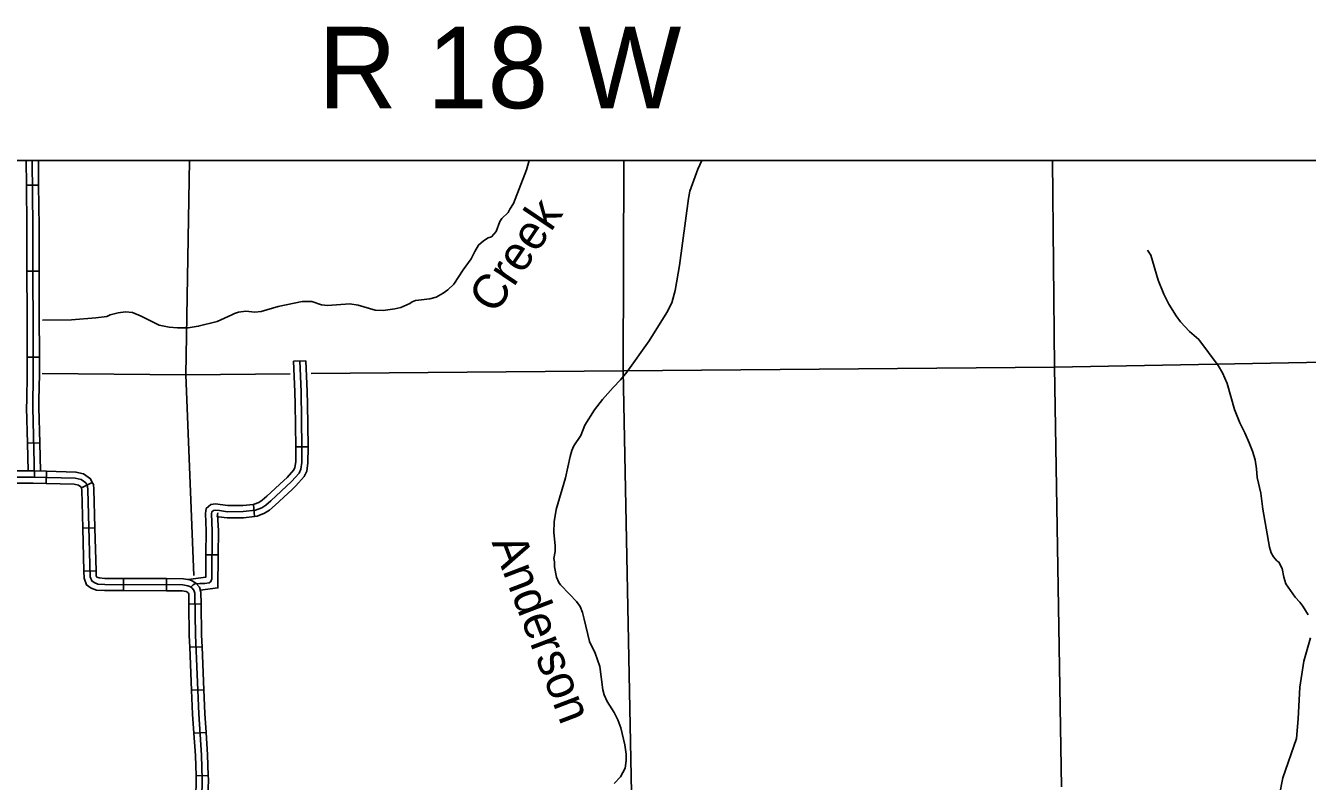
# Model space of a CAD drawing. Extents: x 1373862 to 1376999, y 1168398 to 1170455.
# Drawn here: x 1375095.6 to 1375410.3, y 1169426.9 to 1169612.5 of the extents above; entities that cross this region are included whole.
import ezdxf

# ---------------------------------------------------------------- set-up
doc = ezdxf.new("R2010")
doc.units = 0
for name, color, linetype in [('Level 32', 7, 'Continuous'), ('Level 35', 7, 'Continuous'), ('Level 45', 7, 'Continuous'), ('Level 5', 7, 'Continuous'), ('Level 8', 7, 'Continuous'), ('R_Draft', 7, 'Continuous')]:
    doc.layers.add(name, color=color, linetype=linetype)

msp = doc.modelspace()

# ---------------------------------------------------------------- linework, layer by layer
at = {"layer": 'Level 32'}
for p, q in [((1375100.63, 1169500.05), (1375100.71, 1169503.05)), ((1375109.25, 1169498.98), (1375111.93, 1169500.32)), ((1375109.58, 1169489.09), (1375112.58, 1169489.17)), ((1375109.86, 1169478.54), (1375112.86, 1169478.62)), ((1375119.59, 1169473.73), (1375119.6, 1169476.73)), ((1375130.15, 1169473.69), (1375130.16, 1169476.69)), ((1375135.64, 1169470.42), (1375138.64, 1169470.47)), ((1375135.87, 1169459.82), (1375138.87, 1169459.95)), ((1375136.32, 1169449.27), (1375139.32, 1169449.4)), ((1375136.88, 1169438.7), (1375139.87, 1169438.89)), ((1375137.39, 1169428.2), (1375140.39, 1169428.29))]:
    msp.add_line(p, q, dxfattribs=at)
for points in [[(1375090.11, 1169503.13), (1375097.42, 1169503.14), (1375100.71, 1169503.05)], [(1375100.71, 1169503.05), (1375107.89, 1169502.86), (1375109.78, 1169502.42), (1375111.49, 1169501.21), (1375111.93, 1169500.32)], [(1375063.64, 1169501.6), (1375097.4, 1169501.64), (1375107.7, 1169501.36), (1375109.15, 1169501.02), (1375110.31, 1169500.2), (1375110.72, 1169499.38), (1375110.83, 1169498.52), (1375111.39, 1169477.11), (1375111.77, 1169476.1), (1375112.37, 1169475.69), (1375113.3, 1169475.36), (1375114.98, 1169475.24), (1375134.15, 1169475.17), (1375135.42, 1169474.95), (1375135.9, 1169474.72), (1375136.39, 1169474.39), (1375136.87, 1169473.83), (1375137.1, 1169473.12), (1375137.25, 1169462.78), (1375138.07, 1169443.48), (1375138.74, 1169433.3), (1375138.92, 1169427.3), (1375138.81, 1169422.79)], [(1375090.12, 1169500.13), (1375097.38, 1169500.14), (1375100.63, 1169500.05)], [(1375100.63, 1169500.05), (1375107.51, 1169499.87), (1375108.53, 1169499.63), (1375109.14, 1169499.2), (1375109.25, 1169498.98)], [(1375109.25, 1169498.98), (1375109.27, 1169498.94), (1375109.34, 1169498.4), (1375109.58, 1169489.09)], [(1375111.93, 1169500.32), (1375112.18, 1169499.82), (1375112.33, 1169498.64), (1375112.58, 1169489.17)], [(1375109.58, 1169489.09), (1375109.86, 1169478.54)], [(1375112.58, 1169489.17), (1375112.86, 1169478.62)], [(1375109.86, 1169478.54), (1375109.9, 1169476.83), (1375110.53, 1169475.14), (1375111.68, 1169474.35), (1375112.99, 1169473.87), (1375114.93, 1169473.75), (1375119.59, 1169473.73)], [(1375112.86, 1169478.62), (1375112.89, 1169477.4), (1375113.01, 1169477.07), (1375113.06, 1169477.04), (1375113.61, 1169476.84), (1375115.03, 1169476.74), (1375119.6, 1169476.73)], [(1375119.6, 1169476.73), (1375130.16, 1169476.69)], [(1375119.59, 1169473.73), (1375130.15, 1169473.69)], [(1375130.15, 1169473.69), (1375134.01, 1169473.67), (1375134.97, 1169473.5), (1375135.16, 1169473.41), (1375135.38, 1169473.26), (1375135.54, 1169473.08), (1375135.6, 1169472.87), (1375135.64, 1169470.42)], [(1375130.16, 1169476.69), (1375134.28, 1169476.67), (1375135.87, 1169476.39), (1375136.65, 1169476.03), (1375137.4, 1169475.51), (1375138.21, 1169474.57), (1375138.59, 1169473.36), (1375138.64, 1169470.47)], [(1375138.64, 1169470.47), (1375138.75, 1169462.82), (1375138.87, 1169459.95)], [(1375135.64, 1169470.42), (1375135.75, 1169462.73), (1375135.87, 1169459.82)], [(1375135.87, 1169459.82), (1375136.32, 1169449.27)], [(1375138.87, 1169459.95), (1375139.32, 1169449.4)], [(1375136.32, 1169449.27), (1375136.57, 1169443.4), (1375136.88, 1169438.7)], [(1375139.32, 1169449.4), (1375139.57, 1169443.57), (1375139.87, 1169438.89)], [(1375136.88, 1169438.7), (1375137.24, 1169433.23), (1375137.39, 1169428.2)], [(1375139.87, 1169438.89), (1375140.23, 1169433.38), (1375140.39, 1169428.29)], [(1375137.39, 1169428.2), (1375137.42, 1169427.3), (1375137.31, 1169422.87), (1375136.93, 1169417.82)], [(1375140.39, 1169428.29), (1375140.42, 1169427.31), (1375140.31, 1169422.72), (1375139.92, 1169417.59)]]:
    msp.add_lwpolyline(points, dxfattribs=at)
at = {"layer": 'Level 35'}
for points in [[(1375099.73, 1169540.16), (1375106.79, 1169540.27), (1375112.76, 1169540.73), (1375115.51, 1169541.11), (1375116.32, 1169541.47), (1375118.25, 1169541.96), (1375120.1, 1169542.19), (1375121.79, 1169542.04), (1375123.93, 1169541.15), (1375128.35, 1169538.98), (1375130.84, 1169538.43), (1375132.87, 1169538.3), (1375135.45, 1169538.33), (1375137.96, 1169538.7), (1375142.59, 1169539.87), (1375146.17, 1169541.45), (1375146.84, 1169541.85), (1375147.85, 1169542.15), (1375149.6, 1169542.42), (1375151.85, 1169542.14), (1375153.36, 1169542.3), (1375157.55, 1169543.5), (1375163.48, 1169544.78), (1375165.86, 1169544.74), (1375168.18, 1169543.98), (1375169.71, 1169543.74), (1375175.16, 1169544.19), (1375177.19, 1169543.84), (1375181.42, 1169542.63), (1375183.36, 1169542.54), (1375186.21, 1169542.98), (1375187.66, 1169543.32), (1375189.88, 1169544.28), (1375190.51, 1169544.7), (1375191.26, 1169545), (1375194.83, 1169545.38), (1375196.36, 1169545.82), (1375198.09, 1169546.81), (1375199.27, 1169547.64), (1375200.67, 1169549), (1375203.02, 1169552.58), (1375204.99, 1169555.24), (1375205.83, 1169557.05), (1375206.8, 1169558.64), (1375207.98, 1169559.69), (1375209.16, 1169560.37), (1375209.93, 1169560.67), (1375211.14, 1169561.92), (1375211.97, 1169564.43), (1375212.49, 1169565.15), (1375214.04, 1169566.64), (1375214.43, 1169567.45), (1375215.36, 1169568.82), (1375218.56, 1169577.11), (1375219.24, 1169579.43)], [(1375261.57, 1169579.43), (1375260.64, 1169577.31), (1375258.7, 1169571.86), (1375258.31, 1169570.07), (1375256.14, 1169553.58), (1375255.04, 1169547.47), (1375254.22, 1169544.44), (1375253, 1169542.1), (1375248.66, 1169535.12), (1375243.22, 1169527.37), (1375241.63, 1169525.51), (1375239.86, 1169523.67), (1375237.18, 1169520.67), (1375235.24, 1169518.15), (1375232.84, 1169514.38), (1375231.93, 1169511.86), (1375230.15, 1169509.31), (1375229.68, 1169508.19), (1375229.24, 1169506.7), (1375228.14, 1169501.47), (1375225.8, 1169493.67), (1375225.34, 1169490.6), (1375225.29, 1169488.01), (1375225.59, 1169484.81), (1375225.63, 1169483.33), (1375225.26, 1169481.63), (1375225.4, 1169480.81), (1375225.45, 1169479.59), (1375225.94, 1169477.04), (1375226.49, 1169475.71), (1375226.88, 1169475.16), (1375229.07, 1169472.83), (1375230.85, 1169471.09), (1375231.7, 1169469.87), (1375232.32, 1169468.36), (1375232.74, 1169466.75)], [(1375371.05, 1169557.4), (1375371.87, 1169556.12), (1375373.69, 1169549.99), (1375375.08, 1169546.57), (1375376.28, 1169544.12), (1375378.06, 1169541.26), (1375379.14, 1169539.74), (1375381.38, 1169537.43), (1375383.65, 1169535.41), (1375388.42, 1169529.04), (1375389.46, 1169527.24), (1375390.59, 1169524.6), (1375392.4, 1169518.27), (1375393.72, 1169514.96), (1375394.95, 1169512.48), (1375395.99, 1169510.08), (1375396.83, 1169507.96), (1375397.52, 1169505.83), (1375397.82, 1169503.67), (1375397.98, 1169501.51), (1375398.88, 1169497.7), (1375399.4, 1169493.72), (1375401.02, 1169484.4), (1375401.44, 1169483.02), (1375401.96, 1169482.07), (1375402.81, 1169481.09), (1375403.34, 1169480.73), (1375404.1, 1169479.18), (1375404.54, 1169477.01), (1375405, 1169475.43), (1375407.34, 1169472.13), (1375408.48, 1169470.89), (1375409.2, 1169469.93), (1375410.54, 1169467.82)], [(1375232.74, 1169466.75), (1375234.01, 1169461.26), (1375235.4, 1169458.39), (1375236.57, 1169455.09), (1375237.32, 1169449.4), (1375237.61, 1169448.12), (1375238.33, 1169446.53), (1375240.1, 1169443.81), (1375241.01, 1169442.01), (1375241.7, 1169440.06), (1375242.69, 1169435.84), (1375242.99, 1169433.54), (1375243.05, 1169432.04), (1375242.76, 1169430.14), (1375241.66, 1169428.01), (1375240.1, 1169426.38)], [(1375411.1, 1169462.16), (1375409.42, 1169456.37), (1375408.48, 1169450.05), (1375408.06, 1169442.25), (1375407.63, 1169437.39), (1375404.32, 1169427.73), (1375403.4, 1169423.15)]]:
    msp.add_lwpolyline(points, dxfattribs=at)
at = {"layer": 'Level 45'}
for p, q in [((1375095.75, 1169573.31), (1375098.75, 1169573.34)), ((1375095.88, 1169552.2), (1375098.88, 1169552.21)), ((1375095.92, 1169531.08), (1375098.92, 1169531.09)), ((1375161.36, 1169530.09), (1375164.35, 1169530.22)), ((1375096.03, 1169509.93), (1375099.03, 1169510.01)), ((1375161.91, 1169509.02), (1375164.91, 1169509.07)), ((1375151.47, 1169494.93), (1375151.79, 1169491.95)), ((1375139.84, 1169482.53), (1375142.84, 1169482.51))]:
    msp.add_line(p, q, dxfattribs=at)
for points in [[(1375095.69, 1169579.43), (1375095.75, 1169573.31)], [(1375097.19, 1169579.43), (1375097.36, 1169563.21), (1375097.43, 1169526.92), (1375097.29, 1169518.67), (1375097.75, 1169501.63)], [(1375098.69, 1169579.43), (1375098.75, 1169573.34)], [(1375095.75, 1169573.31), (1375095.86, 1169563.2), (1375095.86, 1169562.76)], [(1375098.75, 1169573.34), (1375098.86, 1169563.22), (1375098.86, 1169562.77)], [(1375095.86, 1169562.76), (1375095.88, 1169552.2)], [(1375098.86, 1169562.77), (1375098.88, 1169552.21)], [(1375095.88, 1169552.2), (1375095.9, 1169541.64)], [(1375098.88, 1169552.21), (1375098.9, 1169541.65)], [(1375095.9, 1169541.64), (1375095.92, 1169531.08)], [(1375098.9, 1169541.65), (1375098.92, 1169531.09)], [(1375095.92, 1169531.08), (1375095.93, 1169526.93), (1375095.82, 1169520.55)], [(1375098.92, 1169531.09), (1375098.93, 1169526.91), (1375098.82, 1169520.5)], [(1375162.85, 1169530.16), (1375163.18, 1169522.57), (1375163.41, 1169508.99), (1375163.38, 1169505.23), (1375163.12, 1169503.54), (1375162.69, 1169502.59), (1375160.84, 1169500.51), (1375155.8, 1169495.83), (1375154.55, 1169494.74), (1375153.52, 1169494.08), (1375152.01, 1169493.48), (1375148.97, 1169493.15), (1375145.15, 1169493.12), (1375143.14, 1169493.38), (1375142.15, 1169493.52), (1375141.69, 1169493.45), (1375141.29, 1169493.12), (1375141.19, 1169492.56), (1375141.39, 1169488.41), (1375141.29, 1169476.6), (1375141.06, 1169475.95), (1375140.6, 1169475.62), (1375139.58, 1169475.48), (1375138.36, 1169475.48), (1375137.11, 1169475.38), (1375136.68, 1169475.12), (1375136.14, 1169474.56)], [(1375161.36, 1169530.09), (1375161.68, 1169522.53), (1375161.73, 1169519.58)], [(1375164.35, 1169530.22), (1375164.68, 1169522.62), (1375164.73, 1169519.63)], [(1375095.82, 1169520.55), (1375095.79, 1169518.66), (1375096.03, 1169509.93)], [(1375098.82, 1169520.5), (1375098.79, 1169518.68), (1375099.03, 1169510.01)], [(1375161.73, 1169519.58), (1375161.91, 1169509.02)], [(1375164.73, 1169519.63), (1375164.91, 1169509.07)], [(1375096.03, 1169509.93), (1375096.21, 1169503.14)], [(1375099.03, 1169510.01), (1375099.21, 1169503.09)], [(1375161.91, 1169509.02), (1375161.91, 1169508.98), (1375161.88, 1169505.35), (1375161.67, 1169503.97), (1375161.41, 1169503.41), (1375159.77, 1169501.56), (1375158.94, 1169500.79)], [(1375164.91, 1169509.07), (1375164.92, 1169509), (1375164.88, 1169505.1), (1375164.57, 1169503.11), (1375163.96, 1169501.76), (1375161.92, 1169499.46), (1375160.98, 1169498.59)], [(1375158.94, 1169500.79), (1375154.8, 1169496.94), (1375153.64, 1169495.94), (1375152.84, 1169495.42), (1375151.65, 1169494.95), (1375151.47, 1169494.93)], [(1375160.98, 1169498.59), (1375156.8, 1169494.71), (1375155.45, 1169493.53), (1375154.21, 1169492.74), (1375152.37, 1169492.01), (1375151.79, 1169491.95)], [(1375139.81, 1169493.33), (1375139.69, 1169492.66), (1375139.89, 1169488.39), (1375139.84, 1169482.53)], [(1375151.47, 1169494.93), (1375148.89, 1169494.65), (1375145.24, 1169494.62), (1375143.34, 1169494.87), (1375142.14, 1169495.03), (1375141.05, 1169494.88), (1375139.91, 1169493.92), (1375139.81, 1169493.33)], [(1375151.79, 1169491.95), (1375149.06, 1169491.65), (1375145.06, 1169491.62), (1375142.94, 1169491.9), (1375142.61, 1169491.94), (1375142.76, 1169492.81)], [(1375142.76, 1169492.81), (1375142.7, 1169492.46), (1375142.89, 1169488.44), (1375142.84, 1169482.51)], [(1375139.84, 1169482.53), (1375139.8, 1169477.02), (1375135.45, 1169476.46)], [(1375142.84, 1169482.51), (1375142.77, 1169474.38), (1375138.45, 1169473.82)]]:
    msp.add_lwpolyline(points, dxfattribs=at)
at = {"layer": 'Level 5'}
for points in [[(1375242.42, 1169579.43), (1375242.3, 1169527.75)], [(1375347.75, 1169579.43), (1375348.25, 1169528.62)], [(1375348.25, 1169528.62), (1375454.3, 1169530.61)], [(1375099.63, 1169527.11), (1375134.88, 1169526.76)], [(1375165.64, 1169527.04), (1375242.3, 1169527.75)], [(1375242.3, 1169527.75), (1375348.25, 1169528.62)], [(1375242.3, 1169527.75), (1375244.34, 1169424.04)], [(1375348.25, 1169528.62), (1375349.94, 1169425.54)], [(1375134.88, 1169526.76), (1375160.54, 1169527)]]:
    msp.add_lwpolyline(points, dxfattribs=at)
at = {"layer": 'Level 8'}
msp.add_lwpolyline([(1375136.84, 1169477.42), (1375134.88, 1169526.76), (1375135.8, 1169579.43)], dxfattribs=at)
at = {"layer": 'R_Draft'}
msp.add_lwpolyline([(1374675.34, 1169579.43), (1376182.76, 1169579.43), (1376182.76, 1168562.99), (1374675.34, 1168562.99)], close=True, dxfattribs=at)

# ---------------------------------------------------------------- texts
at = {"layer": 'Level 35'}
for s, rotation, p in [('Creek', 56.0081, (1375210.84, 1169541.37)), ('Anderson', 290.8562, (1375209.94, 1169485.61))]:
    msp.add_text(s, height=8.448, rotation=rotation, dxfattribs=at).set_placement(p)
at = {"layer": 'R_Draft'}
msp.add_text('R 18 W', height=20, dxfattribs=at).set_placement((1375167.39, 1169592.24))

doc.saveas('drawing.dxf')
